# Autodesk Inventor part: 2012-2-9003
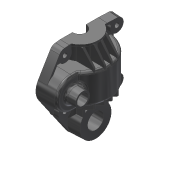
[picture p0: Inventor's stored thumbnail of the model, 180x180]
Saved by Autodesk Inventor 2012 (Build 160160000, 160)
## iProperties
Created: 2011-12
Part Number: 2012-2-9003
Material: Default
Document SubType Name: Modeling
Designer: Admin
Density: 1 g/cm^3
Description: Right Gear Box
Author: Admin
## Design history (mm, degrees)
node "2012-2-9002" dims "d0" = 10
feature "2012-2-9003::2012-2-9002" dims "d0" = 10
tag "TaggingFeature1"
body "Solid1"
